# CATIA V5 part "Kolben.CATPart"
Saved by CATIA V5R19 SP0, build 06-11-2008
Part number: kolben
Bounding box of the stored display mesh (mm): x 0 to 30, y -26.905 to 26.905, z -20 to 33.719
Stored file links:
  H:\Bachelorarbeit_Hahn\Neue Vereinfachung\Kolben.CATPart
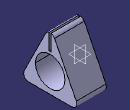
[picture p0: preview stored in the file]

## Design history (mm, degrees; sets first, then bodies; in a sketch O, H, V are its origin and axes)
Body1 (main body)
  Sketch1 on yz-plane, origin (0, 0, 0), H (0, 1, 0), V (0, 0, 1)
    line L1 (-21.9098, -20) -> (21.9098, -20)
    line L2 (-4.4721, 31.0557) -> (-26.382, -12.7639)
    point P1 (0, 40)
    line L3 (4.4721, 31.0557) -> (26.382, -12.7639)
    arc A1 centre (0, 28.8197) radius 5 from (4.4721, 31.0557) to (-4.4721, 31.0557) ccw
    arc A2 centre (21.9098, -15) radius 5 from (21.9098, -20) to (26.382, -12.7639) ccw
    arc A3 centre (-21.9098, -15) radius 5 from (-26.382, -12.7639) to (-21.9098, -20) ccw
    radius A1 = 5
    radius A2 = 5
    radius A3 = 5
    horizontal: L1 H
    coincidence: P1 V, L3 P1, L2 P1
    tangency: A1 L3, A1 L2, A2 L1, A2 L3, A3 L2, A3 L1
  Pad1: profile Sketch1, direction (1, 0, 0), length 30
  Sketch2 on end face of Pad1, origin (30, 0, 0), H (0, 1, 0), V (0, 0, 1)
    circle A1 centre (0, 0) radius 15
    radius A1 = 15
  Pad2: profile Sketch2, direction (-1, 0, 0), length 30
  Pocket1: profile Sketch2, direction (-1, 0, 0), length 30
  Sketch3 on face of Pad2, origin (30, 0, 0), H (0, 1, 0), V (0, 0, 1)
    point P1 (0, 26.39)
    line L1 (1, 35.39) -> (1, 17.39)
    line L2 (1, 17.39) -> (-1, 17.39)
    line L3 (-1, 17.39) -> (-1, 35.39)
    line L4 (-1, 35.39) -> (1, 35.39)
    distance L1 L3 = 2
    distance L4 L2 = 18
    coincidence: P1 V
    vertical: L1 V, L3 V
    horizontal: L2 H, L4 H
    equidistance: L1 L3 P1, L2 L4 P1
  Pad3: profile Sketch3, direction (-1, 0, 0), length 30
  Pocket2: profile Sketch3, direction (-1, 0, 0), length 30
